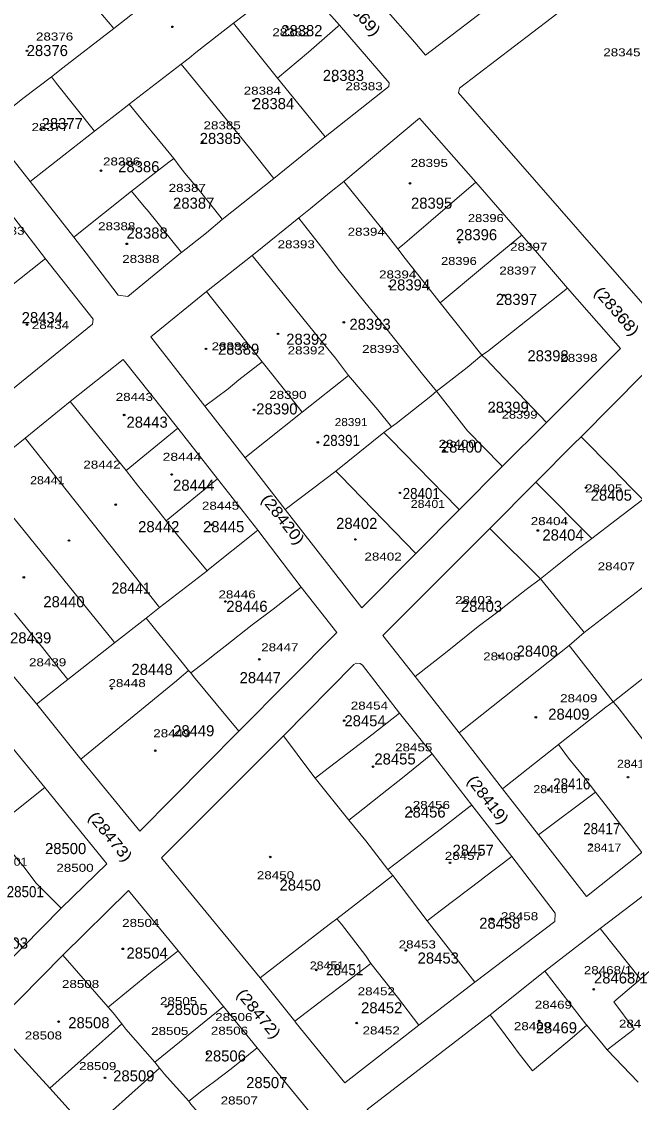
# Model space of a CAD drawing. Extents: x 650553 to 652508, y 239277 to 241647.
# Drawn here: x 651530.5 to 651729.3, y 240724.2 to 241075.2 of the extents above; entities that cross this region are included whole.
import ezdxf

# ---------------------------------------------------------------- set-up
doc = ezdxf.new("R2010")
doc.units = 0
doc.header["$PDMODE"] = 32
doc.header["$PDSIZE"] = 0.5
for name, color, linetype in [('19', 7, 'Continuous'), ('20', 7, 'Continuous'), ('6', 7, 'Continuous')]:
    doc.layers.add(name, color=color, linetype=linetype)
doc.layers.add('3', color=7, linetype='Continuous', lineweight=13)
doc.layers.add('5', color=7, linetype='Continuous', lineweight=13)

msp = doc.modelspace()

# ---------------------------------------------------------------- linework, layer by layer
at = {"layer": '3'}
for p, q in [((651590.53, 240987.56), (651605.33, 240999.25)), ((651682.45, 240910.61), (651697.38, 240925.64)), ((651543.3, 240787.26), (651530.84, 240774.62)), ((651522.14, 240750), (651543.89, 240772.06)), ((651677.55, 240763.24), (651659.4, 240749.316)), ((651606.935, 240741.896), (651595.97, 240755.31))]:
    msp.add_line(p, q, dxfattribs=at)
for points in [[(651521.1, 241173.57), (651534.93, 241185.86), (651536.21, 241185.9), (651559.68, 241158.88), (651574.64, 241141.61), (651589.38, 241124.56), (651604.36, 241107.45), (651619.46, 241090.15), (651633.6, 241074.05)], [(651737.63, 240981.45), (651733.68, 240981.72), (651717.72, 241000), (651672.26, 241052.06), (651672.58, 241053.6), (651750, 241112.87), (651779.79, 241135.68), (651785.77, 241140.28)], [(651683.02, 241080.71), (651661.58, 241064.36), (651658.09, 241068.4), (651637.53, 241091.91), (651626.47, 241104.9), (651615.22, 241117.65)], [(651633.6, 241074.05), (651649.78, 241055.38), (651649.62, 241054.11), (651629.01, 241037.85), (651612.29, 241024.33), (651595.6, 241010.96)], [(651635.06, 241023.32), (651659.573, 241043.894), (651677.93, 241023.1)], [(651582.04, 241000), (651565, 240985.97), (651561.78, 240986.38), (651551.43, 241000), (651547.43, 241005.26), (651533.21, 241023.25), (651519.26, 241040.99)], [(651620.43, 241011.48), (651624.21, 241014.54), (651630.42, 241019.58), (651635.06, 241023.32)], [(651707.67, 240988.67), (651697.95, 241000), (651692.87, 241005.92), (651677.93, 241023.1)], [(651524.41, 241016.3), (651536.85, 241000), (651538.21, 240998.22)], [(651605.33, 240999.25), (651606.26, 241000), (651620.43, 241011.48)], [(651595.6, 241010.96), (651590.46, 241006.61), (651582.39, 241000.29), (651582.04, 241000)], [(651538.21, 240998.22), (651553.74, 240978.64), (651553.52, 240976.92), (651526.98, 240955.44), (651509.19, 240941.06)], [(651589.95, 240950.32), (651572.38, 240972.85), (651590.53, 240987.56)], [(651707.67, 240988.67), (651724.88, 240969.03), (651700.8, 240945.07)], [(651581.17, 240943.18), (651563.4, 240965.53), (651546.27, 240951.81)], [(651712.06, 240940.35), (651732.06, 240960.6), (651750, 240940.5)], [(651546.27, 240951.81), (651531.67, 240939.91), (651516.66, 240927.91), (651501.92, 240915.97)], [(651616.01, 240916.82), (651602.99, 240933.56), (651589.95, 240950.32)], [(651700.8, 240945.07), (651686.45, 240930.79), (651672.54, 240916.66), (651658.42, 240902.54)], [(651621.23, 240891.54), (651607.11, 240910.02), (651594.03, 240926.76), (651581.17, 240943.18)], [(651697.38, 240925.64), (651709.75, 240938.14), (651712.06, 240940.35)], [(651658.42, 240902.54), (651640.9, 240884.82), (651616.01, 240916.82)], [(651658.2, 240862.55), (651647.73, 240875.86), (651682.45, 240910.61)], [(651600.94, 240844.75), (651632.76, 240876.83), (651621.23, 240891.54)], [(651514.54, 240878.38), (651535.4, 240853.59), (651549.69, 240835.74)], [(651499.31, 240873.72), (651511.23, 240859.29), (651523.5, 240844.24), (651538, 240826.47)], [(651615.43, 240843.27), (651638.28, 240866.39), (651639.09, 240866.89), (651640.33, 240866.8), (651641.13, 240866.21), (651653.16, 240850.65)], [(651698.26, 240811.09), (651686.58, 240826.06), (651672.48, 240844.29), (651658.2, 240862.55)], [(651653.16, 240850.65), (651663.75, 240837.46), (651676.59, 240820.8), (651689.56, 240804.04)], [(651549.69, 240835.74), (651568.85, 240812.36), (651600.94, 240844.75)], [(651607.87, 240764.63), (651575.87, 240803.68), (651615.43, 240843.27)], [(651538, 240826.47), (651558.16, 240801.75), (651543.3, 240787.26)], [(651731.81, 240805.34), (651713.76, 240791.05), (651698.26, 240811.09)], [(651689.56, 240804.04), (651703.59, 240785.69), (651703.49, 240783), (651677.55, 240763.24)], [(651666.816, 240692.253), (651642.596, 240721.898), (651682.54, 240752.71), (651700.34, 240766.81), (651718.3, 240780.69), (651736.3, 240794.4)], [(651543.89, 240772.06), (651565.16, 240793.03), (651581.26, 240773.4), (651595.97, 240755.31)], [(651530.84, 240774.62), (651513.67, 240757.48), (651502.8, 240769.36)], [(651619.61, 240750), (651619.13, 240750.6), (651607.87, 240764.63)], [(651522.14, 240750), (651521.163, 240749.011), (651539.59, 240728.862)], [(651619.61, 240750), (651635.372, 240730.625), (651659.4, 240749.316)], [(651603.824, 240702.804), (651623.93, 240721.142), (651606.935, 240741.896)], [(651539.59, 240728.862), (651552.382, 240714.704), (651565.174, 240700.661)]]:
    msp.add_lwpolyline(points, dxfattribs=at)
at = {"layer": '5'}
for p, q in [((651582.22, 241061.38), (651565.41, 241048.37)), ((651665.18, 240955.17), (651666.48, 240956.2)), ((651648.03, 240941.81), (651650.31, 240939.53)), ((651633.94, 240927.7), (651658.42, 240902.54)), ((651577.36, 240913.11), (651581.07, 240908.42)), ((651537.239, 240871.964), (651528.17, 240883.13)), ((651716.78, 240824.93), (651698.26, 240811.09)), ((651632.8, 240783.88), (651650.96, 240797.88)), ((651650.96, 240797.88), (651649.35, 240799.87)), ((651543.89, 240772.06), (651558.557, 240755.154)), ((651573.717, 240737.3), (651595.97, 240755.31)), ((651730.541, 240730.757), (651720.55, 240741.246))]:
    msp.add_line(p, q, dxfattribs=at)
for points in [[(651589.38, 241124.56), (651588.88, 241124.159), (651580.7, 241117.59), (651578.54, 241116.06), (651550.77, 241094.48), (651545.7, 241090.47), (651560.44, 241073), (651568.43, 241079.26)], [(651619.46, 241090.15), (651618.96, 241089.772), (651609.27, 241082.45), (651608.66, 241081.92), (651599.23, 241074.74), (651613.57, 241056.87)], [(651599.23, 241074.74), (651594.96, 241071.32), (651586.97, 241065.21), (651584.93, 241063.46), (651582.22, 241061.38), (651584.36, 241058.95), (651590.13, 241051.78), (651604.42, 241034.28)], [(651519.26, 241040.99), (651519.76, 241041.387), (651530.89, 241050.22), (651540.19, 241057.3), (651543.85, 241060.18), (651560.44, 241073)], [(651633.6, 241074.05), (651633.1, 241073.616), (651623.54, 241065.31), (651613.57, 241056.87)], [(651540.19, 241057.3), (651541.84, 241055.15), (651554.13, 241039.63), (651544.14, 241031.82)], [(651613.57, 241056.87), (651628.604, 241038.35), (651629.01, 241037.85)], [(651565.41, 241048.37), (651564.17, 241047.41), (651554.13, 241039.63)], [(651565.41, 241048.37), (651568.72, 241044.32), (651576.41, 241034.97), (651579.85, 241030.78), (651581.98, 241027.93), (651583.49, 241026.06), (651588.08, 241020.44)], [(651604.42, 241034.28), (651611.895, 241024.83), (651612.29, 241024.33)], [(651544.14, 241031.82), (651533.71, 241023.642), (651533.21, 241023.25)], [(651547.43, 241005.26), (651547.93, 241005.656), (651566.18, 241020.12), (651572.54, 241025.13), (651578.22, 241029.56), (651579.85, 241030.78)], [(651635.06, 241023.32), (651649.59, 241005.29), (651652.63, 241001.46), (651653.71, 241000)], [(651652.63, 241001.46), (651654.13, 241002.63), (651656.4, 241004.61), (651677.93, 241023.1)], [(651566.18, 241020.12), (651569.69, 241015.8), (651570.86, 241014.47), (651571.21, 241014.06), (651582.39, 241000.29)], [(651588.08, 241020.44), (651595.203, 241011.46), (651595.6, 241010.96)], [(651620.43, 241011.48), (651620.819, 241010.98), (651625.94, 241004.39), (651629.3, 241000)], [(651692.87, 241005.92), (651692.37, 241005.509), (651685.66, 241000)], [(651513.35, 240978.58), (651537.71, 240997.825), (651538.21, 240998.22)], [(651625.47, 240974.41), (651605.735, 240998.75), (651605.33, 240999.25)], [(651641.88, 240984.14), (651633.69, 240994.28), (651629.3, 241000)], [(651685.66, 241000), (651680.03, 240995.38), (651666.3, 240983.94), (651663.15, 240987.94), (651654.57, 240998.82), (651653.71, 241000)], [(651590.53, 240987.56), (651608.58, 240964.71), (651600.96, 240958.88), (651597.5, 240955.95), (651589.95, 240950.32)], [(651707.67, 240988.67), (651681.71, 240968.12), (651679.87, 240966.85)], [(651641.88, 240984.14), (651648.56, 240975.87), (651660.59, 240960.75), (651665.18, 240955.17), (651663.24, 240953.61), (651652.08, 240944.76), (651650.57, 240943.67)], [(651679.87, 240966.85), (651670.562, 240978.611), (651666.3, 240983.94)], [(651636.62, 240960.3), (651632.31, 240965.89), (651628.32, 240970.85), (651627.1, 240972.3), (651625.47, 240974.41)], [(651679.87, 240966.85), (651675.13, 240962.852), (651666.48, 240956.2)], [(651679.87, 240966.85), (651681.45, 240965.41), (651682.8, 240963.99), (651700.8, 240945.07)], [(651608.58, 240964.71), (651617.51, 240953.49), (651621.57, 240948.37)], [(651621.57, 240948.37), (651636.62, 240960.3), (651646.14, 240949.15), (651650.57, 240943.67)], [(651665.18, 240955.17), (651675.18, 240942.37), (651685.963, 240931.29), (651686.45, 240930.79)], [(651546.27, 240951.81), (651564.43, 240929.45), (651581.17, 240943.18)], [(651621.57, 240948.37), (651603.49, 240933.959), (651602.99, 240933.56)], [(651632.46, 240929.28), (651648.03, 240941.81), (651650.57, 240943.67)], [(651531.67, 240939.91), (651532.066, 240939.41), (651574.851, 240885.404), (651575.247, 240884.904)], [(651650.31, 240939.53), (651672.054, 240917.16), (651672.54, 240916.66)], [(651750, 240934.8), (651733.48, 240921.37), (651732.05, 240920.07), (651728.26, 240923.78), (651722.22, 240930.07), (651712.06, 240940.35)], [(651564.43, 240929.45), (651568.09, 240924.69), (651573.72, 240917.79), (651575, 240916.14), (651577.36, 240913.11)], [(651616.01, 240916.82), (651624.89, 240923.5), (651632.46, 240929.28), (651633.94, 240927.7)], [(651518.73, 240925.21), (651560.268, 240873.976), (651560.673, 240873.476)], [(651577.36, 240913.11), (651593.53, 240926.351), (651594.03, 240926.76)], [(651715.51, 240907.39), (651697.877, 240925.14), (651697.38, 240925.64)], [(651732.05, 240920.07), (651723.48, 240913.44), (651715.51, 240907.39)], [(651713.094, 240876.806), (651767.9, 240919.045), (651768.4, 240919.43)], [(651590.666, 240896.859), (651591.166, 240897.259), (651606.61, 240909.62), (651607.11, 240910.02)], [(651713.094, 240876.806), (651712.687, 240877.306), (651698.85, 240894.29), (651682.45, 240910.61)], [(651581.07, 240908.42), (651590.666, 240896.859), (651575.247, 240884.904), (651570.862, 240881.504)], [(651715.51, 240907.39), (651710.39, 240903.47), (651703.72, 240898.13), (651698.85, 240894.29), (651694.24, 240890.78), (651684.62, 240883.22), (651678.64, 240878.75), (651668.01, 240870.26), (651658.2, 240862.55)], [(651621.23, 240891.54), (651612.14, 240884.37), (651605.34, 240879.34), (651596.53, 240872.39), (651592.62, 240869.37), (651589.79, 240867.1), (651585.4, 240863.75), (651586.24, 240862.5), (651600.94, 240844.75)], [(651570.862, 240881.504), (651560.673, 240873.476), (651545.51, 240861.53), (651543.56, 240860.06)], [(651585.4, 240863.75), (651584.61, 240864.53), (651582.2, 240867.6), (651575.44, 240875.88), (651570.862, 240881.504)], [(651672.48, 240844.29), (651672.98, 240844.685), (651708.23, 240872.56), (651713.094, 240876.806)], [(651708.23, 240872.56), (651708.622, 240872.06), (651722.51, 240854.34), (651740.3, 240868.43), (651750, 240876.09)], [(651537.239, 240871.964), (651542.8, 240864.9), (651545.51, 240861.53)], [(651549.69, 240835.74), (651580.72, 240861.18), (651584.61, 240864.53)], [(651543.56, 240860.06), (651535.9, 240853.986), (651535.4, 240853.59)], [(651722.51, 240854.34), (651720.05, 240852.59), (651704.72, 240840.47)], [(651722.51, 240854.34), (651723.48, 240853.25), (651724.39, 240852.09), (651749.66, 240819.26)], [(651625.76, 240829.52), (651630.35, 240833.12), (651644.11, 240843.62), (651653.16, 240850.65)], [(651615.43, 240843.27), (651624.35, 240831.41), (651625.76, 240829.52), (651636.73, 240815.86), (651642.16, 240809.13), (651649.35, 240799.87)], [(651704.72, 240840.47), (651687.08, 240826.457), (651686.58, 240826.06)], [(651704.72, 240840.47), (651707.99, 240836.04), (651712.92, 240829.92), (651716.78, 240824.93), (651719.91, 240820.96), (651723.46, 240816.36), (651731.81, 240805.34)], [(651663.75, 240837.46), (651663.25, 240837.054), (651654.06, 240829.6), (651647.49, 240824.41), (651641.19, 240819.5), (651636.73, 240815.86)], [(651538, 240826.47), (651521.21, 240813.2), (651524.67, 240808.76), (651529.34, 240802.91), (651531.25, 240800.58)], [(651676.59, 240820.8), (651676.09, 240820.411), (651666.79, 240813.18), (651653.83, 240803.33), (651649.35, 240799.87)], [(651662.08, 240783.22), (651666.79, 240786.74), (651679.58, 240796.5), (651680.32, 240797.02), (651689.56, 240804.04)], [(651531.25, 240800.58), (651535.11, 240795.54), (651543.3, 240787.26)], [(651650.96, 240797.88), (651662.08, 240783.22), (651677.55, 240763.24)], [(651521.26, 240784.29), (651523.72, 240781.48), (651530.84, 240774.62)], [(651607.87, 240764.63), (651630.25, 240781.96), (651632.8, 240783.88), (651634.25, 240782.06)], [(651634.25, 240782.06), (651642.22, 240771.79), (651643.84, 240769.38), (651652.51, 240758.39), (651659.4, 240749.316)], [(651718.3, 240780.69), (651718.697, 240780.19), (651731.34, 240764.27), (651734.39, 240766.92), (651736.58, 240764.83), (651750, 240751.45)], [(651581.26, 240773.4), (651580.76, 240773.008), (651572.34, 240766.4)], [(651643.84, 240769.38), (651641.93, 240767.9), (651628.81, 240757.99), (651619.13, 240750.6)], [(651572.34, 240766.4), (651559.057, 240755.562), (651558.557, 240755.154)], [(651700.34, 240766.81), (651700.726, 240766.31), (651713.645, 240749.592)], [(651731.34, 240764.27), (651722.71, 240756.86), (651729.289, 240747.993), (651720.55, 240741.246)], [(651558.557, 240755.154), (651560.206, 240753.253), (651563.01, 240749.685)], [(651682.54, 240752.71), (651682.913, 240752.21), (651684.56, 240750)], [(651573.717, 240737.3), (651564.302, 240748.003), (651563.01, 240749.685), (651560.747, 240747.728), (651539.59, 240728.862)], [(651684.56, 240750), (651690.201, 240742.417), (651691.66, 240740.443), (651696.328, 240734.523), (651708.39, 240744.504), (651713.876, 240749.301), (651713.645, 240749.592)], [(651713.876, 240749.301), (651719.195, 240742.877), (651720.55, 240741.246)], [(651584.715, 240724.6), (651588.926, 240727.979), (651593.101, 240730.99), (651598.476, 240735.125), (651606.935, 240741.896)], [(651552.382, 240714.704), (651552.882, 240715.156), (651572.363, 240732.75), (651573.247, 240733.606), (651575.193, 240735.321), (651573.717, 240737.3)], [(651575.193, 240735.321), (651576.07, 240734.35), (651576.791, 240733.5)], [(651587.592, 240721.16), (651585.419, 240723.664), (651584.715, 240724.6), (651576.791, 240733.5)]]:
    msp.add_lwpolyline(points, dxfattribs=at)
at = {"layer": '6'}
for p in [(651579.43, 241073.54), (651616.598, 241073.51), (651532.206, 241065.73), (651631.801, 241055.95), (651605.744, 241049.535), (651536.721, 241040.275), (651589.15, 241036.17), (651556.229, 241026.815), (651656.508, 241022.677), (651580.947, 241015.535), (651564.634, 241003.045), (651672.549, 241003.52), (651649.939, 240989.245), (651687.009, 240986.385), (651532.217, 240976.83), (651635.043, 240977.575), (651613.663, 240973.81), (651590.334, 240968.94), (651701.304, 240966.87), (651605.918, 240949.135), (651683.687, 240948.82), (651563.761, 240947.49), (651626.627, 240938.56), (651667.643, 240935.915), (651579.189, 240928.145), (651713.656, 240923.87), (651653.248, 240922.175), (651561.001, 240918.357), (651592.051, 240911.809), (651698.025, 240909.965), (651545.864, 240906.693), (651638.821, 240907.05), (651531.205, 240894.72), (651596.565, 240886.885), (651673.668, 240886.58), (651607.619, 240868.145), (651685.435, 240869.29), (651559.673, 240858.622), (651635.16, 240848.205), (651697.365, 240849.31), (651573.841, 240838.445), (651644.547, 240833.255), (651727.249, 240829.84), (651701.46, 240825.78), (651657.006, 240818.665), (651715.23, 240807.99), (651540.086, 240806.865), (651611.161, 240803.95), (651669.504, 240802.01), (651683.078, 240783.64), (651563.322, 240774.092), (651655.173, 240773.598), (651626.148, 240767.24), (651716.174, 240760.968), (651577.367, 240755.35), (651542.497, 240750.461), (651639.244, 240750.002), (651698.439, 240750.666), (651590.754, 240739.955), (651557.537, 240732.194)]:
    msp.add_point(p, dxfattribs=at)

# ---------------------------------------------------------------- texts
at = {"layer": '19'}
for s, rotation, width, p in [('(28369)', 311.292, 1.15, (651632.029, 241084.512)), ('(28368)', 311.011, 1.15, (651716.05, 240987.226)), ('(28420)', 308.09, 1.15, (651608.013, 240920.023)), ('(28419)', 307.622, 1.1, (651674.874, 240828.655)), ('(28473)', 309.198, 1.15, (651551.868, 240816.813)), ('(28472)', 309.26, 1.15, (651600.042, 240759.301))]:
    msp.add_text(s, height=3.6, rotation=rotation, dxfattribs=dict(at, width=width)).set_placement(p)
for s, p in [('28382', (651614.732, 241070.502)), ('28376', (651532.118, 241064.036)), ('28383', (651628.231, 241055.954)), ('28384', (651605.552, 241046.794)), ('28377', (651536.977, 241040.328)), ('28385', (651588.274, 241035.478)), ('28386', (651561.817, 241026.318)), ('28387', (651579.636, 241014.464)), ('28395', (651656.85, 241014.464)), ('28388', (651564.515, 241004.765)), ('28396', (651671.429, 241004.226)), ('28394', (651649.657, 240987.916)), ('28397', (651684.388, 240983.212)), ('28434', (651530.496, 240977.285)), ('28393', (651636.871, 240975.13)), ('28392', (651616.352, 240970.28)), ('28389', (651594.214, 240967.047)), ('28398', (651694.647, 240964.892)), ('28399', (651681.688, 240948.188)), ('28390', (651606.632, 240947.649)), ('28443', (651564.515, 240943.34)), ('28400', (651666.569, 240935.256)), ('28444', (651579.634, 240922.864)), ('28405', (651715.165, 240919.631)), ('28442', (651568.295, 240909.394)), ('28445', (651589.353, 240909.394)), ('28402', (651632.551, 240910.471)), ('28404', (651699.506, 240906.699)), ('28440', (651537.525, 240885.016)), ('28446', (651596.913, 240883.53)), ('28403', (651673.048, 240883.53)), ('28439', (651526.717, 240873.292)), ('28408', (651691.135, 240868.981)), ('28448', (651566.135, 240863.055)), ('28447', (651601.232, 240860.361)), ('28454', (651635.25, 240846.352)), ('28409', (651701.394, 240848.505)), ('28449', (651579.634, 240843.118)), ('28455', (651644.969, 240833.959)), ('28456', (651654.69, 240816.717)), ('28500', (651538.058, 240804.863)), ('28457', (651670.349, 240804.324)), ('28450', (651614.191, 240793.008)), ('28458', (651678.987, 240780.615)), ('28503', (651519.16, 240774.15)), ('28504', (651564.514, 240770.916)), ('28453', (651659.008, 240769.3)), ('28468/1', (651716.245, 240762.834)), ('28505', (651577.473, 240752.596)), ('28452', (651640.649, 240753.135)), ('28508', (651545.615, 240748.285)), ('28469', (651697.346, 240746.669)), ('28506', (651589.893, 240737.508)), ('28509', (651560.195, 240731.043)), ('28507', (651603.343, 240728.854))]:
    msp.add_text(s, height=3.6, dxfattribs=at).set_placement(p)
for s, width, p in [('28391', 0.9, (651628.231, 240937.412)), ('28401', 0.9, (651654.15, 240920.169)), ('28441', 0.95, (651559.655, 240889.457)), ('28416', 0.9, (651703.015, 240825.873)), ('28417', 0.9, (651712.734, 240811.325)), ('28501', 0.9, (651525.639, 240790.853)), ('28451', 0.9, (651629.31, 240765.528))]:
    msp.add_text(s, height=3.6, dxfattribs=dict(at, width=width)).set_placement(p)
at = {"layer": '20'}
for s, width, p in [('28376', 1.25, (651535.141, 241069.086)), ('28382', 1.25, (651611.851, 241070.478)), ('28345', 1.25, (651719.263, 241063.952)), ('28384', 1.25, (651602.559, 241051.502)), ('28383', 1.25, (651635.584, 241052.94)), ('28385', 1.25, (651589.515, 241040.246)), ('28377', 1.25, (651533.702, 241039.689)), ('28386', 1.25, (651556.896, 241028.513)), ('28395', 1.25, (651656.754, 241028.044)), ('28387', 1.25, (651578.197, 241019.934)), ('28396', 1.2, (651675.337, 241010.129)), ('28433', 1.25, (651519.331, 241006.011)), ('28388', 1.25, (651555.307, 241007.471)), ('28394', 1.25, (651636.281, 241005.689)), ('28393', 1.25, (651613.552, 241001.614)), ('28397', 1.25, (651689.021, 241000.794)), ('28388', 1.25, (651563.13, 240996.861)), ('28396', 1.2, (651666.6, 240996.199)), ('28394', 1.25, (651646.486, 240991.819)), ('28397', 1.25, (651685.509, 240993.073)), ('28434', 1.25, (651533.786, 240975.383)), ('28389', 1.25, (651592.132, 240968.468)), ('28392', 1.25, (651616.816, 240967.155)), ('28393', 1.25, (651640.988, 240967.622)), ('28398', 1.25, (651705.314, 240964.721)), ('28390', 1.25, (651610.845, 240952.712)), ('28443', 1.25, (651561.021, 240952.044)), ('28399', 1.2, (651686.296, 240946.276)), ('28391', 1.1, (651632.104, 240943.871)), ('28400', 1.25, (651665.824, 240936.804)), ('28444', 1.3, (651576.241, 240932.589)), ('28442', 1.25, (651550.514, 240930.056)), ('28441', 1.15, (651533.255, 240924.991)), ('28405', 1.25, (651713.365, 240922.336)), ('28445', 1.25, (651588.993, 240916.709)), ('28401', 1.15, (651656.791, 240917.297)), ('28404', 1.25, (651695.706, 240911.705)), ('28402', 1.25, (651641.753, 240900.191)), ('28407', 1.25, (651717.436, 240897.029)), ('28446', 1.25, (651594.364, 240887.894)), ('28403', 1.25, (651671.171, 240886.072)), ('28447', 1.25, (651608.234, 240870.724)), ('28439', 1.25, (651532.872, 240865.857)), ('28408', 1.25, (651680.275, 240867.767)), ('28448', 1.25, (651558.675, 240859.1)), ('28409', 1.25, (651705.249, 240854.185)), ('28454', 1.25, (651637.306, 240851.787)), ('28449', 1.25, (651573.204, 240842.813)), ('28455', 1.25, (651651.694, 240838.231)), ('28415', 1.15, (651723.713, 240832.903)), ('28416', 1.15, (651696.574, 240824.649)), ('28456', 1.25, (651657.428, 240819.521)), ('28417', 1.15, (651713.994, 240805.7)), ('28457', 1.25, (651667.825, 240802.991)), ('28501', 1.15, (651521.231, 240801.089)), ('28500', 1.25, (651541.757, 240799.111)), ('28450', 1.25, (651606.826, 240796.698)), ('28504', 1.25, (651563.105, 240781.209)), ('28458', 1.25, (651686.047, 240783.38)), ('28453', 1.25, (651652.843, 240774.225)), ('28451', 1.15, (651624.016, 240767.394)), ('28468/1', 1.25, (651712.947, 240765.863)), ('28508', 1.25, (651543.568, 240761.377)), ('28452', 1.25, (651639.556, 240759.009)), ('28505', 1.25, (651575.38, 240755.798)), ('28469', 1.25, (651697.02, 240754.655)), ('28506', 1.25, (651593.305, 240750.635)), ('28505', 1.25, (651572.503, 240746.118)), ('28506', 1.25, (651591.89, 240746.194)), ('28452', 1.25, (651641.135, 240746.295)), ('28469', 1.25, (651690.246, 240747.677)), ('28468/1', 1.25, (651724.332, 240748.48)), ('28508', 1.25, (651531.497, 240744.656)), ('28509', 1.25, (651549.129, 240734.714)), ('28507', 1.25, (651595.073, 240723.541))]:
    msp.add_text(s, height=2.6, dxfattribs=dict(at, width=width)).set_placement(p)

doc.saveas('drawing.dxf')
